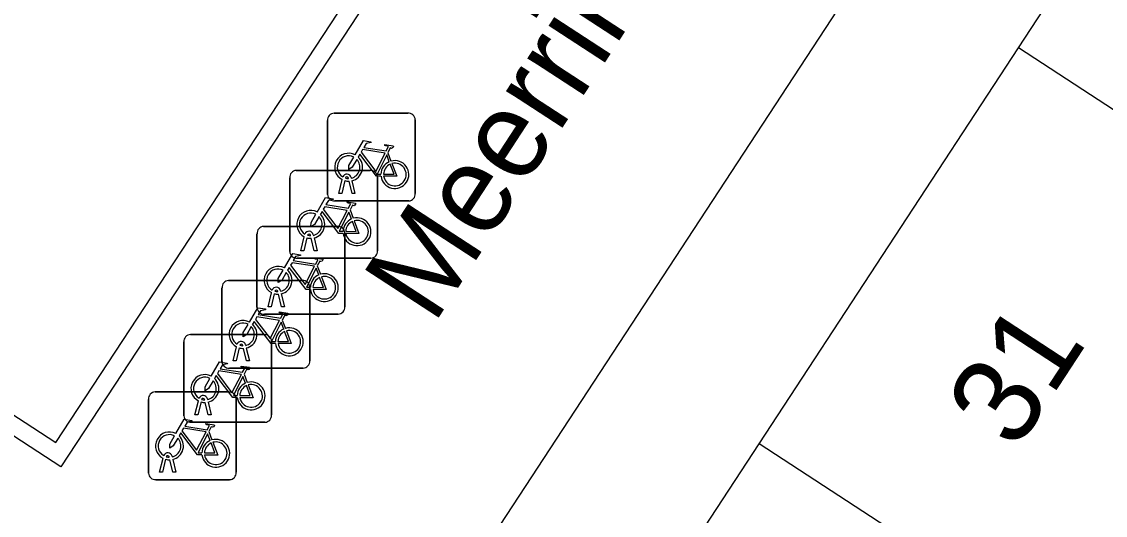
# Model space of a CAD drawing. Extents: x 155640 to 156810, y 382822 to 384046.
# Drawn here: x 156449.06 to 156461.41, y 383730.47 to 383736.1 of the extents above; entities that cross this region are included whole.
import ezdxf

# ---------------------------------------------------------------- set-up
doc = ezdxf.new("R2010")
doc.units = 0
for name, color, linetype in [('IMGEO_Fietsenrek', 7, 'Continuous'), ('IMGEO_Lijnafwatering', 7, 'Continuous'), ('IMGEO_Muur', 7, 'Continuous'), ('IMGEO_Openbare_ruimte_label', 7, 'Continuous'), ('IMGEO_Pand', 7, 'Continuous'), ('IMGEO_Pand_nummerreeks', 7, 'Continuous')]:
    doc.layers.add(name, color=color, linetype=linetype)

msp = doc.modelspace()

# ---------------------------------------------------------------- linework, layer by layer
at = {"layer": 'IMGEO_Fietsenrek'}
for p, q in [((156452.618, 383735.057), (156453.459, 383735.057)), ((156453.459, 383735.057), (156452.618, 383735.057)), ((156452.543, 383734.132), (156452.543, 383734.973)), ((156452.543, 383734.973), (156452.543, 383734.132)), ((156453.543, 383734.982), (156453.543, 383734.141)), ((156453.543, 383734.141), (156453.543, 383734.982)), ((156453.23, 383734.606), (156453.266, 383734.511)), ((156452.187, 383734.405), (156453.028, 383734.405)), ((156453.028, 383734.405), (156452.187, 383734.405)), ((156452.112, 383733.48), (156452.112, 383734.321)), ((156452.112, 383734.321), (156452.112, 383733.48)), ((156452.67, 383734.141), (156452.709, 383734.301)), ((156452.739, 383734.289), (156452.704, 383734.141)), ((156452.781, 383734.313), (156452.78, 383734.317)), ((156452.822, 383734.141), (156452.788, 383734.283)), ((156452.812, 383734.324), (156452.813, 383734.317)), ((156452.82, 383734.287), (156452.855, 383734.141)), ((156453.112, 383734.33), (156453.112, 383733.489)), ((156453.112, 383733.489), (156453.112, 383734.33)), ((156452.704, 383734.141), (156452.67, 383734.141)), ((156452.855, 383734.141), (156452.822, 383734.141)), ((156453.468, 383734.057), (156452.627, 383734.057)), ((156452.627, 383734.057), (156453.468, 383734.057)), ((156452.799, 383733.954), (156452.835, 383733.859)), ((156451.739, 383732.842), (156451.739, 383733.683)), ((156451.739, 383733.683), (156451.739, 383732.842)), ((156451.814, 383733.767), (156452.655, 383733.767)), ((156452.655, 383733.767), (156451.814, 383733.767)), ((156452.239, 383733.489), (156452.278, 383733.649)), ((156452.35, 383733.661), (156452.349, 383733.665)), ((156452.381, 383733.672), (156452.382, 383733.665)), ((156452.739, 383733.692), (156452.739, 383732.851)), ((156452.739, 383732.851), (156452.739, 383733.692)), ((156452.308, 383733.637), (156452.273, 383733.489)), ((156452.391, 383733.489), (156452.357, 383733.631)), ((156452.389, 383733.635), (156452.424, 383733.489)), ((156453.037, 383733.405), (156452.196, 383733.405)), ((156452.196, 383733.405), (156453.037, 383733.405)), ((156452.273, 383733.489), (156452.239, 383733.489)), ((156452.424, 383733.489), (156452.391, 383733.489)), ((156452.426, 383733.316), (156452.462, 383733.221)), ((156451.34, 383732.225), (156451.34, 383733.066)), ((156451.34, 383733.066), (156451.34, 383732.225)), ((156451.415, 383733.15), (156452.256, 383733.15)), ((156452.256, 383733.15), (156451.415, 383733.15)), ((156451.977, 383733.023), (156451.976, 383733.027)), ((156452.008, 383733.034), (156452.009, 383733.027)), ((156452.34, 383733.075), (156452.34, 383732.234)), ((156452.34, 383732.234), (156452.34, 383733.075)), ((156451.866, 383732.851), (156451.905, 383733.011)), ((156451.935, 383732.999), (156451.9, 383732.851)), ((156452.018, 383732.851), (156451.984, 383732.993)), ((156452.016, 383732.997), (156452.051, 383732.851)), ((156451.9, 383732.851), (156451.866, 383732.851)), ((156452.051, 383732.851), (156452.018, 383732.851)), ((156452.664, 383732.767), (156451.823, 383732.767)), ((156451.823, 383732.767), (156452.664, 383732.767)), ((156452.027, 383732.699), (156452.063, 383732.604)), ((156450.905, 383731.608), (156450.905, 383732.449)), ((156450.905, 383732.449), (156450.905, 383731.608)), ((156450.98, 383732.533), (156451.821, 383732.533)), ((156451.821, 383732.533), (156450.98, 383732.533)), ((156451.578, 383732.406), (156451.577, 383732.41)), ((156451.609, 383732.417), (156451.61, 383732.41)), ((156451.905, 383732.458), (156451.905, 383731.617)), ((156451.905, 383731.617), (156451.905, 383732.458)), ((156451.467, 383732.234), (156451.506, 383732.394)), ((156451.536, 383732.382), (156451.501, 383732.234)), ((156451.619, 383732.234), (156451.585, 383732.376)), ((156451.617, 383732.38), (156451.652, 383732.234)), ((156451.501, 383732.234), (156451.467, 383732.234)), ((156451.652, 383732.234), (156451.619, 383732.234)), ((156452.265, 383732.15), (156451.424, 383732.15)), ((156451.424, 383732.15), (156452.265, 383732.15)), ((156451.592, 383732.082), (156451.628, 383731.987)), ((156450.502, 383730.954), (156450.502, 383731.795)), ((156450.502, 383731.795), (156450.502, 383730.954)), ((156450.577, 383731.879), (156451.418, 383731.879)), ((156451.418, 383731.879), (156450.577, 383731.879)), ((156451.143, 383731.789), (156451.142, 383731.793)), ((156451.174, 383731.8), (156451.175, 383731.793)), ((156451.502, 383731.804), (156451.502, 383730.963)), ((156451.502, 383730.963), (156451.502, 383731.804)), ((156451.032, 383731.617), (156451.071, 383731.777)), ((156451.101, 383731.765), (156451.066, 383731.617)), ((156451.184, 383731.617), (156451.15, 383731.759)), ((156451.182, 383731.763), (156451.217, 383731.617)), ((156451.066, 383731.617), (156451.032, 383731.617)), ((156451.217, 383731.617), (156451.184, 383731.617)), ((156451.83, 383731.533), (156450.989, 383731.533)), ((156450.989, 383731.533), (156451.83, 383731.533)), ((156451.189, 383731.428), (156451.225, 383731.333)), ((156450.629, 383730.963), (156450.668, 383731.123)), ((156450.698, 383731.111), (156450.663, 383730.963)), ((156450.74, 383731.135), (156450.739, 383731.139)), ((156450.781, 383730.963), (156450.747, 383731.105)), ((156450.771, 383731.146), (156450.772, 383731.139)), ((156450.779, 383731.109), (156450.814, 383730.963)), ((156450.663, 383730.963), (156450.629, 383730.963)), ((156450.814, 383730.963), (156450.781, 383730.963)), ((156451.427, 383730.879), (156450.586, 383730.879)), ((156450.586, 383730.879), (156451.427, 383730.879))]:
    msp.add_line(p, q, dxfattribs=at)
for points in [[(156452.856, 383734.583), (156452.951, 383734.747), (156453.037, 383734.733), (156453.039, 383734.724), (156452.983, 383734.713), (156452.956, 383734.668), (156453.212, 383734.627)], [(156453.199, 383734.602), (156452.942, 383734.643), (156452.925, 383734.614), (156453.092, 383734.394), (156453.199, 383734.602)], [(156453.212, 383734.627), (156453.237, 383734.676), (156453.231, 383734.68), (156453.208, 383734.684), (156453.196, 383734.691), (156453.195, 383734.694), (156453.197, 383734.699), (156453.292, 383734.684), (156453.294, 383734.674), (156453.284, 383734.661), (156453.272, 383734.655), (156453.258, 383734.661), (156453.23, 383734.606)], [(156452.877, 383734.531), (156452.825, 383734.441), (156452.785, 383734.416), (156452.786, 383734.463), (156452.841, 383734.557)], [(156453.152, 383734.339), (156453.102, 383734.339), (156452.911, 383734.59), (156452.892, 383734.558)], [(156453.247, 383734.504), (156453.217, 383734.581), (156453.108, 383734.363), (156453.151, 383734.363)], [(156453.181, 383734.363), (156453.301, 383734.362), (156453.257, 383734.476)], [(156453.277, 383734.483), (156453.332, 383734.338), (156453.182, 383734.338)], [(156452.425, 383733.931), (156452.52, 383734.095), (156452.606, 383734.081), (156452.608, 383734.072), (156452.552, 383734.061), (156452.525, 383734.016), (156452.781, 383733.975)], [(156452.781, 383733.975), (156452.806, 383734.024), (156452.8, 383734.028), (156452.777, 383734.032), (156452.765, 383734.039), (156452.764, 383734.042), (156452.766, 383734.047), (156452.861, 383734.032), (156452.863, 383734.022), (156452.853, 383734.009), (156452.841, 383734.003), (156452.827, 383734.009), (156452.799, 383733.954)], [(156452.446, 383733.879), (156452.394, 383733.789), (156452.354, 383733.764), (156452.355, 383733.811), (156452.41, 383733.905)], [(156452.721, 383733.687), (156452.671, 383733.687), (156452.48, 383733.938), (156452.461, 383733.906)], [(156452.768, 383733.95), (156452.511, 383733.991), (156452.494, 383733.962), (156452.661, 383733.742), (156452.768, 383733.95)], [(156452.816, 383733.852), (156452.786, 383733.929), (156452.677, 383733.711), (156452.72, 383733.711)], [(156452.75, 383733.711), (156452.87, 383733.71), (156452.826, 383733.824)], [(156452.846, 383733.831), (156452.901, 383733.686), (156452.751, 383733.686)], [(156452.052, 383733.293), (156452.147, 383733.457), (156452.233, 383733.443), (156452.235, 383733.434), (156452.179, 383733.423), (156452.152, 383733.378), (156452.408, 383733.337)], [(156452.408, 383733.337), (156452.433, 383733.386), (156452.427, 383733.39), (156452.404, 383733.394), (156452.392, 383733.401), (156452.391, 383733.404), (156452.393, 383733.409), (156452.488, 383733.394), (156452.49, 383733.384), (156452.48, 383733.371), (156452.468, 383733.365), (156452.454, 383733.371), (156452.426, 383733.316)], [(156452.348, 383733.049), (156452.298, 383733.049), (156452.107, 383733.3), (156452.088, 383733.268)], [(156452.395, 383733.312), (156452.138, 383733.353), (156452.121, 383733.324), (156452.288, 383733.104), (156452.395, 383733.312)], [(156452.443, 383733.214), (156452.413, 383733.291), (156452.304, 383733.073), (156452.347, 383733.073)], [(156452.073, 383733.241), (156452.021, 383733.151), (156451.981, 383733.126), (156451.982, 383733.173), (156452.037, 383733.267)], [(156452.377, 383733.073), (156452.497, 383733.072), (156452.453, 383733.186)], [(156452.473, 383733.193), (156452.528, 383733.048), (156452.378, 383733.048)], [(156451.653, 383732.676), (156451.748, 383732.84), (156451.834, 383732.826), (156451.836, 383732.817), (156451.78, 383732.806), (156451.753, 383732.761), (156452.009, 383732.72)], [(156452.009, 383732.72), (156452.034, 383732.769), (156452.028, 383732.773), (156452.005, 383732.777), (156451.993, 383732.784), (156451.992, 383732.787), (156451.994, 383732.792), (156452.089, 383732.777), (156452.091, 383732.767), (156452.081, 383732.754), (156452.069, 383732.748), (156452.055, 383732.754), (156452.027, 383732.699)], [(156451.949, 383732.432), (156451.899, 383732.432), (156451.708, 383732.683), (156451.689, 383732.651)], [(156451.996, 383732.695), (156451.739, 383732.736), (156451.722, 383732.707), (156451.889, 383732.487), (156451.996, 383732.695)], [(156452.044, 383732.597), (156452.014, 383732.674), (156451.905, 383732.456), (156451.948, 383732.456)], [(156451.674, 383732.624), (156451.622, 383732.534), (156451.582, 383732.509), (156451.583, 383732.556), (156451.638, 383732.65)], [(156451.978, 383732.456), (156452.098, 383732.455), (156452.054, 383732.569)], [(156452.074, 383732.576), (156452.129, 383732.431), (156451.979, 383732.431)], [(156451.218, 383732.059), (156451.313, 383732.223), (156451.399, 383732.209), (156451.401, 383732.2), (156451.345, 383732.189), (156451.318, 383732.144), (156451.574, 383732.103)], [(156451.574, 383732.103), (156451.599, 383732.152), (156451.593, 383732.156), (156451.57, 383732.16), (156451.558, 383732.167), (156451.557, 383732.17), (156451.559, 383732.175), (156451.654, 383732.16), (156451.656, 383732.15), (156451.646, 383732.137), (156451.634, 383732.131), (156451.62, 383732.137), (156451.592, 383732.082)], [(156451.514, 383731.815), (156451.464, 383731.815), (156451.273, 383732.066), (156451.254, 383732.034)], [(156451.561, 383732.078), (156451.304, 383732.119), (156451.287, 383732.09), (156451.454, 383731.87), (156451.561, 383732.078)], [(156451.609, 383731.98), (156451.579, 383732.057), (156451.47, 383731.839), (156451.513, 383731.839)], [(156451.239, 383732.007), (156451.187, 383731.917), (156451.147, 383731.892), (156451.148, 383731.939), (156451.203, 383732.033)], [(156451.543, 383731.839), (156451.663, 383731.838), (156451.619, 383731.952)], [(156451.639, 383731.959), (156451.694, 383731.814), (156451.544, 383731.814)], [(156450.815, 383731.405), (156450.91, 383731.569), (156450.996, 383731.555), (156450.998, 383731.546), (156450.942, 383731.535), (156450.915, 383731.49), (156451.171, 383731.449)], [(156451.158, 383731.424), (156450.901, 383731.465), (156450.884, 383731.436), (156451.051, 383731.216), (156451.158, 383731.424)], [(156451.171, 383731.449), (156451.196, 383731.498), (156451.19, 383731.502), (156451.167, 383731.506), (156451.155, 383731.513), (156451.154, 383731.516), (156451.156, 383731.521), (156451.251, 383731.506), (156451.253, 383731.496), (156451.243, 383731.483), (156451.231, 383731.477), (156451.217, 383731.483), (156451.189, 383731.428)], [(156450.836, 383731.353), (156450.784, 383731.263), (156450.744, 383731.238), (156450.745, 383731.285), (156450.8, 383731.379)], [(156451.111, 383731.161), (156451.061, 383731.161), (156450.87, 383731.412), (156450.851, 383731.38)], [(156451.206, 383731.326), (156451.176, 383731.403), (156451.067, 383731.185), (156451.11, 383731.185)], [(156451.236, 383731.305), (156451.291, 383731.16), (156451.141, 383731.16)], [(156451.14, 383731.185), (156451.26, 383731.184), (156451.216, 383731.298)]]:
    msp.add_lwpolyline(points, dxfattribs=at)
for centre, radius, start, end in [((156452.621, 383734.979), 0.0779, 92.4484, 184.2845), ((156452.621, 383734.979), 0.0779, 92.4484, 184.2845), ((156453.465, 383734.979), 0.0779, 2.4484, 94.2845), ((156453.465, 383734.979), 0.0779, 2.4484, 94.2845), ((156452.783, 383734.442), 0.159, 62.6766, 242.1369), ((156452.783, 383734.442), 0.129, 63.3192, 238.903), ((156452.783, 383734.442), 0.129, 283.6043, 43.4302), ((156452.783, 383734.442), 0.159, 283.5766, 46.6042), ((156453.31, 383734.358), 0.159, 187.0065, 105.7708), ((156452.19, 383734.327), 0.0779, 92.4484, 184.2845), ((156452.19, 383734.327), 0.0779, 92.4484, 184.2845), ((156453.034, 383734.327), 0.0779, 2.4484, 94.2845), ((156453.034, 383734.327), 0.0779, 2.4484, 94.2845), ((156453.31, 383734.358), 0.159, 113.3408, 178.3217), ((156453.31, 383734.358), 0.129, 113.923, 177.9556), ((156453.31, 383734.358), 0.129, 188.6715, 104.5883), ((156452.763, 383734.313), 0.0499, 12.8025, 158.6934), ((156452.783, 383734.442), 0.159, 253.9967, 271.7867), ((156452.763, 383734.313), 0.0174, 12.8025, 163.4502), ((156452.783, 383734.442), 0.129, 253.415, 269.0204), ((156453.465, 383734.135), 0.0779, 272.4484, 4.2845), ((156453.465, 383734.135), 0.0779, 272.4484, 4.2845), ((156452.621, 383734.135), 0.0779, 182.4484, 274.2845), ((156452.621, 383734.135), 0.0779, 182.4484, 274.2845), ((156452.352, 383733.79), 0.159, 62.6766, 242.1369), ((156452.352, 383733.79), 0.129, 63.3192, 238.903), ((156452.352, 383733.79), 0.159, 283.5766, 46.6042), ((156452.352, 383733.79), 0.129, 283.6043, 43.4302), ((156452.879, 383733.706), 0.159, 113.3408, 178.3217), ((156452.879, 383733.706), 0.159, 187.0065, 105.7708), ((156452.879, 383733.706), 0.129, 113.923, 177.9556), ((156452.879, 383733.706), 0.129, 188.6715, 104.5883), ((156451.817, 383733.689), 0.0779, 92.4484, 184.2845), ((156451.817, 383733.689), 0.0779, 92.4484, 184.2845), ((156452.332, 383733.661), 0.0499, 12.8025, 158.6934), ((156452.332, 383733.661), 0.0174, 12.8025, 163.4502), ((156452.352, 383733.79), 0.129, 253.415, 269.0204), ((156452.661, 383733.689), 0.0779, 2.4484, 94.2845), ((156452.661, 383733.689), 0.0779, 2.4484, 94.2845), ((156452.352, 383733.79), 0.159, 253.9967, 271.7867), ((156452.19, 383733.483), 0.0779, 182.4484, 274.2845), ((156452.19, 383733.483), 0.0779, 182.4484, 274.2845), ((156453.034, 383733.483), 0.0779, 272.4484, 4.2845), ((156453.034, 383733.483), 0.0779, 272.4484, 4.2845), ((156451.979, 383733.152), 0.159, 62.6766, 242.1369), ((156451.979, 383733.152), 0.129, 63.3192, 238.903), ((156451.979, 383733.152), 0.129, 283.6043, 43.4302), ((156451.979, 383733.152), 0.159, 283.5766, 46.6042), ((156452.506, 383733.068), 0.159, 113.3408, 178.3217), ((156452.506, 383733.068), 0.159, 187.0065, 105.7708), ((156452.506, 383733.068), 0.129, 113.923, 177.9556), ((156452.506, 383733.068), 0.129, 188.6715, 104.5883), ((156451.418, 383733.072), 0.0779, 92.4484, 184.2845), ((156451.418, 383733.072), 0.0779, 92.4484, 184.2845), ((156451.959, 383733.023), 0.0499, 12.8025, 158.6934), ((156451.959, 383733.023), 0.0174, 12.8025, 163.4502), ((156451.979, 383733.152), 0.129, 253.415, 269.0204), ((156452.262, 383733.072), 0.0779, 2.4484, 94.2845), ((156452.262, 383733.072), 0.0779, 2.4484, 94.2845), ((156451.979, 383733.152), 0.159, 253.9967, 271.7867), ((156451.817, 383732.845), 0.0779, 182.4484, 274.2845), ((156451.817, 383732.845), 0.0779, 182.4484, 274.2845), ((156452.661, 383732.845), 0.0779, 272.4484, 4.2845), ((156452.661, 383732.845), 0.0779, 272.4484, 4.2845), ((156451.58, 383732.535), 0.159, 62.6766, 242.1369), ((156451.58, 383732.535), 0.129, 63.3192, 238.903), ((156451.58, 383732.535), 0.129, 283.6043, 43.4302), ((156451.58, 383732.535), 0.159, 283.5766, 46.6042), ((156452.107, 383732.451), 0.159, 113.3408, 178.3217), ((156452.107, 383732.451), 0.159, 187.0065, 105.7708), ((156452.107, 383732.451), 0.129, 113.923, 177.9556), ((156452.107, 383732.451), 0.129, 188.6715, 104.5883), ((156450.983, 383732.455), 0.0779, 92.4484, 184.2845), ((156450.983, 383732.455), 0.0779, 92.4484, 184.2845), ((156451.56, 383732.406), 0.0499, 12.8025, 158.6934), ((156451.56, 383732.406), 0.0174, 12.8025, 163.4502), ((156451.58, 383732.535), 0.129, 253.415, 269.0204), ((156451.827, 383732.455), 0.0779, 2.4484, 94.2845), ((156451.827, 383732.455), 0.0779, 2.4484, 94.2845), ((156451.58, 383732.535), 0.159, 253.9967, 271.7867), ((156451.418, 383732.228), 0.0779, 182.4484, 274.2845), ((156451.418, 383732.228), 0.0779, 182.4484, 274.2845), ((156452.262, 383732.228), 0.0779, 272.4484, 4.2845), ((156452.262, 383732.228), 0.0779, 272.4484, 4.2845), ((156451.145, 383731.918), 0.159, 62.6766, 242.1369), ((156451.145, 383731.918), 0.129, 63.3192, 238.903), ((156451.145, 383731.918), 0.129, 283.6043, 43.4302), ((156451.145, 383731.918), 0.159, 283.5766, 46.6042), ((156451.672, 383731.834), 0.159, 113.3408, 178.3217), ((156451.672, 383731.834), 0.159, 187.0065, 105.7708), ((156451.672, 383731.834), 0.129, 113.923, 177.9556), ((156451.672, 383731.834), 0.129, 188.6715, 104.5883), ((156450.58, 383731.801), 0.0779, 92.4484, 184.2845), ((156450.58, 383731.801), 0.0779, 92.4484, 184.2845), ((156451.125, 383731.789), 0.0499, 12.8025, 158.6934), ((156451.125, 383731.789), 0.0174, 12.8025, 163.4502), ((156451.145, 383731.918), 0.129, 253.415, 269.0204), ((156451.424, 383731.801), 0.0779, 2.4484, 94.2845), ((156451.424, 383731.801), 0.0779, 2.4484, 94.2845), ((156451.145, 383731.918), 0.159, 253.9967, 271.7867), ((156450.983, 383731.611), 0.0779, 182.4484, 274.2845), ((156450.983, 383731.611), 0.0779, 182.4484, 274.2845), ((156451.827, 383731.611), 0.0779, 272.4484, 4.2845), ((156451.827, 383731.611), 0.0779, 272.4484, 4.2845), ((156450.742, 383731.264), 0.159, 62.6766, 242.1369), ((156450.742, 383731.264), 0.129, 63.3192, 238.903), ((156450.742, 383731.264), 0.129, 283.6043, 43.4302), ((156450.742, 383731.264), 0.159, 283.5766, 46.6042), ((156451.269, 383731.18), 0.159, 113.3408, 178.3217), ((156451.269, 383731.18), 0.159, 187.0065, 105.7708), ((156451.269, 383731.18), 0.129, 188.6715, 104.5883), ((156450.722, 383731.135), 0.0499, 12.8025, 158.6934), ((156451.269, 383731.18), 0.129, 113.923, 177.9556), ((156450.742, 383731.264), 0.159, 253.9967, 271.7867), ((156450.722, 383731.135), 0.0174, 12.8025, 163.4502), ((156450.742, 383731.264), 0.129, 253.415, 269.0204), ((156450.58, 383730.957), 0.0779, 182.4484, 274.2845), ((156450.58, 383730.957), 0.0779, 182.4484, 274.2845), ((156451.424, 383730.957), 0.0779, 272.4484, 4.2845), ((156451.424, 383730.957), 0.0779, 272.4484, 4.2845)]:
    msp.add_arc(centre, radius, start, end, dxfattribs=at)
at = {"layer": 'IMGEO_Lijnafwatering'}
msp.add_lwpolyline([(156459.635, 383738.197), (156449.169, 383722.207)], dxfattribs=at)
at = {"layer": 'IMGEO_Muur'}
for points in [[(156449.505, 383731.026), (156444.177, 383734.498), (156452.207, 383746.705), (156457.498, 383743.199), (156449.505, 383731.026)], [(156455.946, 383743.987), (156452.264, 383746.427), (156444.454, 383734.556), (156449.447, 383731.302), (156452.661, 383736.197)]]:
    msp.add_lwpolyline(points, dxfattribs=at)
at = {"layer": 'IMGEO_Pand'}
for points in [[(156460.417, 383735.804), (156463.375, 383740.324)], [(156457.463, 383731.289), (156460.417, 383735.804)], [(156467.606, 383731.11), (156460.417, 383735.804)], [(156454.503, 383726.765), (156457.463, 383731.289)], [(156464.65, 383726.595), (156457.463, 383731.289)]]:
    msp.add_lwpolyline(points, dxfattribs=at)

# ---------------------------------------------------------------- texts
at = {"layer": 'IMGEO_Openbare_ruimte_label'}
msp.add_text('Meerring', height=1, rotation=56.9137, dxfattribs=at).set_placement((156453.75, 383732.635))
at = {"layer": 'IMGEO_Pand_nummerreeks'}
msp.add_text('31', height=1, rotation=56.803, dxfattribs=at).set_placement((156460.388, 383731.193))

doc.saveas('drawing.dxf')
